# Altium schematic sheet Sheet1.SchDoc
size A4
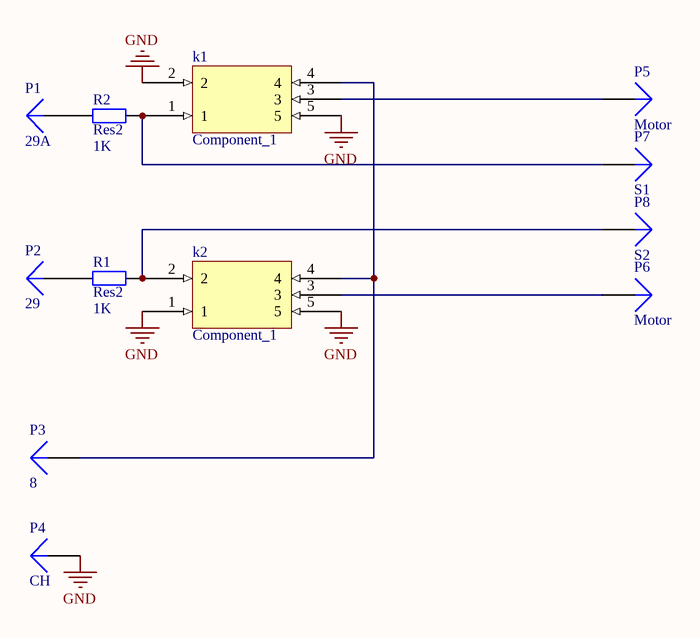
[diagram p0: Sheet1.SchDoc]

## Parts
k1  Component_1  [PCBComponent_1]
k2  Component_1  [PCBComponent_1]
P1  29A  [PIN1]
P2  29  [PIN1]
P3  8  [PIN1]
P4  CH  [PIN1]
P5  Motor  [PIN1]
P6  Motor  [PIN1]
P7  S1  [PIN1]
P8  S2  [PIN1]
R1  Res2  value 1K  [AXIAL-0.7]
R2  Res2  value 1K  [AXIAL-0.7]

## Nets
GND: k1.2 k1.5 k2.1 k2.5 P4.1
Netk1_1: k1.1 P7.1 R2.2
Netk1_3: k1.3 P5.1
Netk1_4: k1.4 k2.4 P3.1
Netk2_2: k2.2 P8.1 R1.2
Netk2_3: k2.3 P6.1
NetP1_1: P1.1 R2.1
NetP2_1: P2.1 R1.1

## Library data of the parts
P1-P8 = Plug
R1 R2 = Res2: Resistor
